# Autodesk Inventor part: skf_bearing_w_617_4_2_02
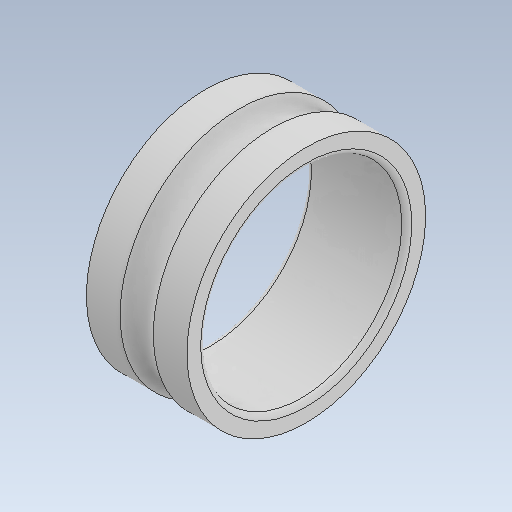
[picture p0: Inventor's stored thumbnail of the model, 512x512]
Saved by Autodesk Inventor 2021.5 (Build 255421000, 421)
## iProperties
Created: 2023-11
Part Number: skf_bearing_w_617_4_2_02
Checked By: TraceParts S.A.
Material: Generic
Catalog Web Link: www.traceparts.com
Document SubType Name: Modeling
Designer: TraceParts
Density: 1 g/cm^3
Appearance: Default
Company: TraceParts S.A.
Author: TraceParts
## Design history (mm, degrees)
feature "skf_bearing_w_617_4_2_02.ipt"
body "Solid1"
